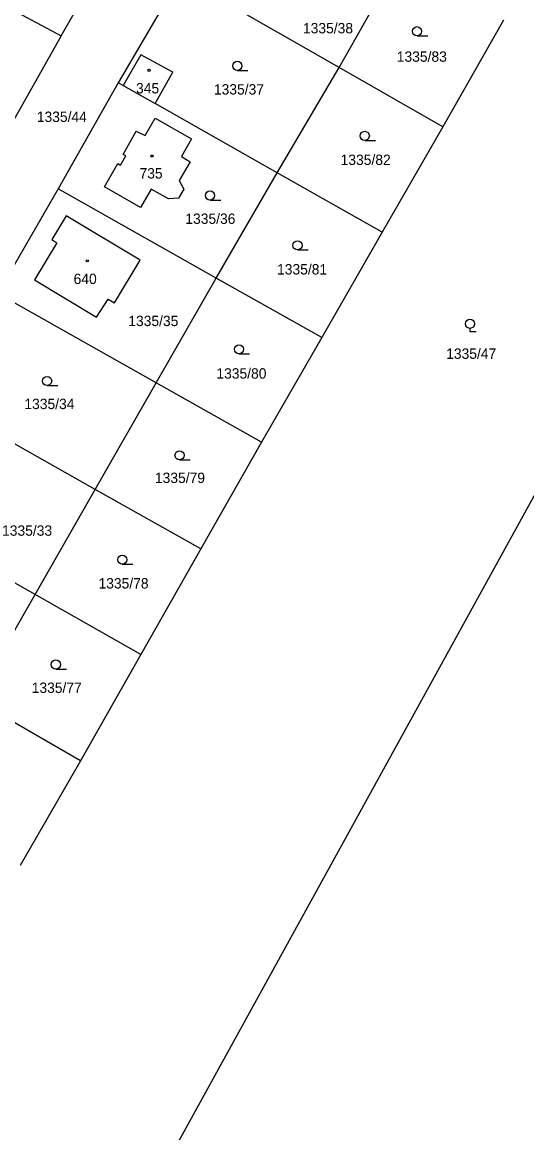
# Model space of a CAD drawing. Extents: x -794765 to -785424, y -1118958 to -1108731.
# Drawn here: x -787867.7 to -787784.9, y -1116978.7 to -1116796.6 of the extents above; entities that cross this region are included whole.
import ezdxf

# ---------------------------------------------------------------- set-up
doc = ezdxf.new("R2010")
doc.units = 0
for name, color, linetype in [('Level 66', 7, 'Continuous'), ('Level 75', 7, 'Continuous'), ('Level 76', 7, 'Continuous'), ('Level 79', 7, 'Continuous')]:
    doc.layers.add(name, color=color, linetype=linetype)

msp = doc.modelspace()

# ---------------------------------------------------------------- linework, layer by layer
at = {"layer": 'Level 66'}
for p, q in [((-787802.92, -1116798.82), (-787801.17, -1116798.82)), ((-787832.41, -1116804.49), (-787830.66, -1116804.49)), ((-787811.49, -1116815.98), (-787809.74, -1116815.98)), ((-787836.88, -1116825.75), (-787835.13, -1116825.75)), ((-787822.52, -1116833.94), (-787820.77, -1116833.94)), ((-787794.23, -1116846.79), (-787794.23, -1116847.29)), ((-787794.23, -1116847.29), (-787793.23, -1116847.29)), ((-787832.13, -1116850.98), (-787830.38, -1116850.98)), ((-787863.61, -1116856.16), (-787861.86, -1116856.16)), ((-787841.88, -1116868.35), (-787840.13, -1116868.35)), ((-787851.27, -1116885.48), (-787849.52, -1116885.48)), ((-787862.18, -1116902.66), (-787860.43, -1116902.66))]:
    msp.add_line(p, q, dxfattribs=at)
for centre in [(-787802.92, -1116798.07), (-787832.41, -1116803.74), (-787811.49, -1116815.23), (-787836.88, -1116825), (-787822.52, -1116833.19), (-787794.23, -1116846.04), (-787832.13, -1116850.23), (-787863.61, -1116855.41), (-787841.88, -1116867.6), (-787851.27, -1116884.73), (-787862.18, -1116901.91)]:
    msp.add_circle(centre, 0.75, dxfattribs=at)
at = {"layer": 'Level 75'}
for p, q in [((-787707.44, -1116735.64), (-787858.42, -1117009.87)), ((-787861.28, -1116798.83), (-787850.23, -1116779.39)), ((-787815.69, -1116804.01), (-787805.83, -1116786.61)), ((-787841.76, -1116789.11), (-787851.94, -1116806.51)), ((-787815.69, -1116804.01), (-787841.76, -1116789.11)), ((-787874.94, -1116791.59), (-787861.28, -1116798.83)), ((-787788.72, -1116796.28), (-787798.66, -1116813.74)), ((-787861.28, -1116798.83), (-787870.53, -1116815.23)), ((-787825.84, -1116821.29), (-787815.69, -1116804.01)), ((-787798.66, -1116813.74), (-787815.69, -1116804.01)), ((-787851.94, -1116806.51), (-787861.82, -1116823.9)), ((-787851.11, -1116806.98), (-787851.94, -1116806.51)), ((-787851.11, -1116806.98), (-787845.89, -1116809.93)), ((-787825.84, -1116821.29), (-787845.89, -1116809.93)), ((-787798.66, -1116813.74), (-787808.62, -1116831.04)), ((-787835.86, -1116838.54), (-787825.84, -1116821.29)), ((-787808.62, -1116831.04), (-787825.84, -1116821.29)), ((-787861.82, -1116823.9), (-787871.75, -1116841.05)), ((-787835.86, -1116838.54), (-787861.82, -1116823.9)), ((-787808.62, -1116831.04), (-787818.55, -1116848.3)), ((-787845.74, -1116855.72), (-787835.86, -1116838.54)), ((-787818.55, -1116848.3), (-787835.86, -1116838.54)), ((-787845.74, -1116855.72), (-787871.75, -1116841.05)), ((-787818.55, -1116848.3), (-787828.43, -1116865.47)), ((-787855.73, -1116873.19), (-787845.74, -1116855.72)), ((-787828.43, -1116865.47), (-787845.74, -1116855.72)), ((-787855.73, -1116873.19), (-787881.69, -1116858.55)), ((-787828.43, -1116865.47), (-787838.37, -1116882.97)), ((-787865.57, -1116890.45), (-787855.73, -1116873.19)), ((-787838.37, -1116882.97), (-787855.73, -1116873.19)), ((-787865.57, -1116890.45), (-787891.61, -1116875.72)), ((-787838.37, -1116882.97), (-787848.21, -1116900.27)), ((-787875.45, -1116907.69), (-787865.57, -1116890.45)), ((-787848.21, -1116900.27), (-787865.57, -1116890.45)), ((-787848.21, -1116900.27), (-787858.14, -1116917.7)), ((-787858.14, -1116917.7), (-787875.45, -1116907.69)), ((-787858.14, -1116917.7), (-787868.02, -1116934.87))]:
    msp.add_line(p, q, dxfattribs=at)
for points in [[(-787845.89, -1116809.93), (-787842.99, -1116804.8), (-787848.25, -1116801.92), (-787851.11, -1116806.98)], [(-787851.14, -1116818.26), (-787848.97, -1116814.43), (-787847.53, -1116815.19), (-787845.88, -1116812.32), (-787839.91, -1116815.69), (-787841.54, -1116818.63), (-787840.16, -1116819.46), (-787841.93, -1116822.52), (-787841.18, -1116823.98), (-787842.03, -1116825.45), (-787843.7, -1116825.56), (-787846.51, -1116823.99), (-787848.3, -1116826.98), (-787854.18, -1116823.61), (-787852, -1116819.78), (-787851.57, -1116820.02), (-787850.71, -1116818.5), (-787851.14, -1116818.26)], [(-787855.5, -1116844.97), (-787853.6, -1116841.99), (-787852.56, -1116842.62), (-787848.36, -1116835.62), (-787860.49, -1116828.33), (-787862.85, -1116832.21), (-787862.01, -1116832.74), (-787865.66, -1116838.84), (-787855.5, -1116844.97)]]:
    msp.add_lwpolyline(points, dxfattribs=at)
at = {"layer": 'Level 79'}
for centre in [(-787846.88, -1116804.47), (-787846.39, -1116818.54), (-787857.01, -1116835.71)]:
    msp.add_circle(centre, 0.175, dxfattribs=at)

# ---------------------------------------------------------------- texts
at = {"layer": 'Level 76'}
for s, p in [('1335/38', (-787821.63, -1116798.42)), ('1335/83', (-787806.24, -1116803.08)), ('345', (-787849.02, -1116808.27)), ('1335/37', (-787836.24, -1116808.45)), ('1335/44', (-787865.3, -1116812.94)), ('1335/82', (-787815.45, -1116820)), ('735', (-787848.45, -1116822.22)), ('1335/36', (-787840.93, -1116829.66)), ('1335/81', (-787825.88, -1116837.96)), ('640', (-787859.26, -1116839.52)), ('1335/35', (-787850.29, -1116846.42)), ('1335/47', (-787798.14, -1116851.79)), ('1335/80', (-787835.84, -1116855.03)), ('1335/34', (-787867.34, -1116860.03)), ('1335/79', (-787845.92, -1116872.15)), ('1335/33', (-787871, -1116880.8)), ('1335/78', (-787855.18, -1116889.45)), ('1335/77', (-787866.14, -1116906.57))]:
    msp.add_text(s, height=1.7, dxfattribs=at).set_placement(p)

doc.saveas('drawing.dxf')
